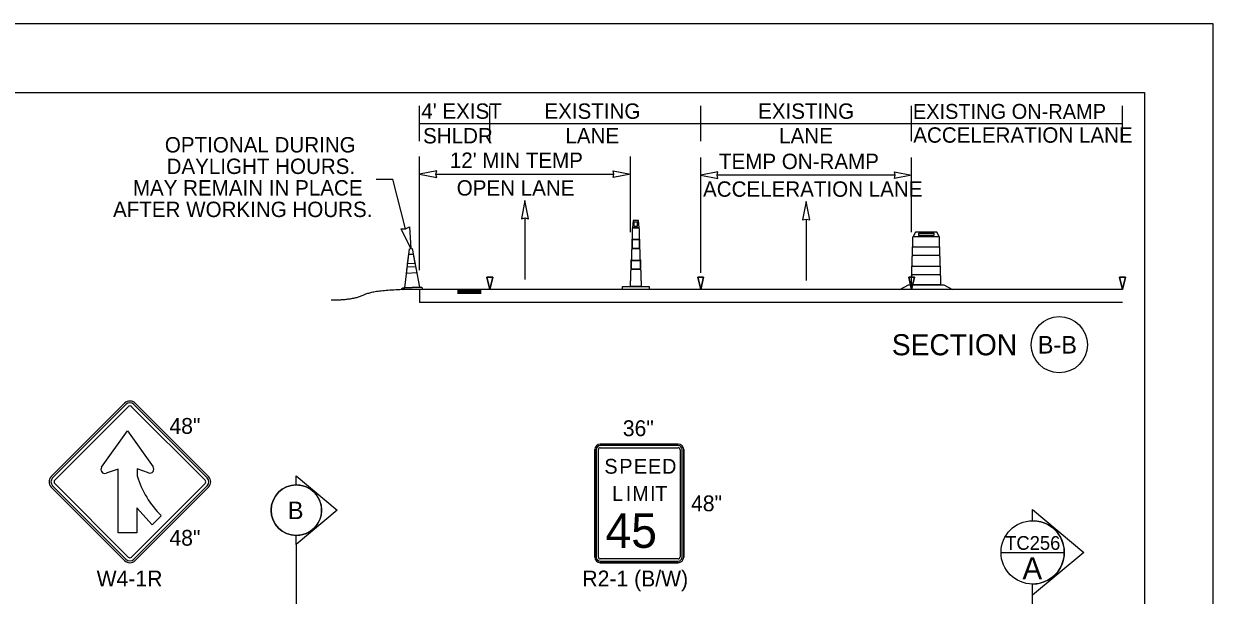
# Model space of a CAD drawing. Extents: x 99999 to 100116, y 99995 to 100013.
# Drawn here: x 100050.65 to 100056.06, y 100008.09 to 100010.69 of the extents above; entities that cross this region are included whole.
import ezdxf

# ---------------------------------------------------------------- set-up
doc = ezdxf.new("R2010")
doc.units = 0
for name, color, linetype in [('SH_GI_PlotLimits', 7, 'Continuous'), ('SH_GI_SectionCut', 7, 'Continuous'), ('SH_GI_SheetBorder', 7, 'Continuous'), ('SH_TI_WZSectionCut', 7, 'Continuous'), ('TR_SN_ConstructionSigns', 7, 'Continuous'), ('TR_WZ_ArrowLeftStrRightTurn', 7, 'Continuous'), ('TR_WZ_TallChanDeviceElev', 7, 'Continuous'), ('TR_WZ_TrafficConeElev', 7, 'Continuous'), ('TR_WZ_TrafficSafetyDrumElev', 7, 'Continuous'), ('TR_WZ_WorkZoneDetails', 7, 'Continuous'), ('TR_WZ_WorkZoneTextCurrent', 7, 'Continuous')]:
    doc.layers.add(name, color=color, linetype=linetype)

msp = doc.modelspace()

# ---------------------------------------------------------------- linework, layer by layer
at = {"layer": 'SH_GI_PlotLimits'}
msp.add_lwpolyline([(100039.0625, 99999.6875), (100056.0625, 99999.6875), (100056.0625, 100010.6875), (100039.0625, 100010.6875)], close=True, dxfattribs=at)
at = {"layer": 'SH_GI_SectionCut'}
for p, q in [((100051.8894, 100008.589), (100051.8894, 100008.6297)), ((100051.8894, 100008.6297), (100052.0755, 100008.4738)), ((100052.0755, 100008.4738), (100051.8894, 100008.3179)), ((100055.2407, 100008.4258), (100055.2407, 100008.4767)), ((100055.2407, 100008.4767), (100055.4733, 100008.2818)), ((100051.8894, 100008.3179), (100051.8894, 100008.3586)), ((100051.8894, 100008.3179), (100051.8894, 100006.8828)), ((100055.4733, 100008.2818), (100055.2407, 100008.0869)), ((100055.2407, 100008.0869), (100055.2407, 100008.1378)), ((100055.2407, 100006.7109), (100055.2407, 100008.0869))]:
    msp.add_line(p, q, dxfattribs=at)
msp.add_lwpolyline([(100055.0967, 100008.2818), (100055.3847, 100008.2818)], dxfattribs=at)
for centre, radius in [((100051.8894, 100008.4738), 0.1152), ((100051.8894, 100008.4738), 0.1152), ((100055.2407, 100008.2818), 0.144)]:
    msp.add_circle(centre, radius, dxfattribs=at)
for centre, radius, start, end in [((100051.8894, 100008.4738), 0.1152, 90.0022, 269.9978), ((100051.8894, 100008.4738), 0.1152, 269.9978, 90.0022), ((100051.8894, 100008.4738), 0.1152, 269.9978, 90.0022), ((100055.2407, 100008.2818), 0.144, 269.9978, 90.0022)]:
    msp.add_arc(centre, radius, start, end, dxfattribs=at)
at = {"layer": 'SH_GI_SheetBorder'}
for p, q in [((100040, 100010.375), (100055.75, 100010.375)), ((100055.75, 100010.375), (100055.75, 100000))]:
    msp.add_line(p, q, dxfattribs=at)
at = {"layer": 'SH_TI_WZSectionCut'}
for p, q in [((100052.45, 100009.5666), (100052.45, 100010.0836)), ((100053.41, 100009.7388), (100053.41, 100010.0836)), ((100052.525, 100010.0036), (100053.335, 100010.0036))]:
    msp.add_line(p, q, dxfattribs=at)
for points in [[(100052.45, 100010.0036), (100052.5286, 100009.9882), (100052.525, 100010.0036), (100052.5286, 100010.019)], [(100053.41, 100010.0036), (100053.3314, 100009.9882), (100053.335, 100010.0036), (100053.3314, 100010.019)]]:
    msp.add_lwpolyline(points, close=True, dxfattribs=at)
at = {"layer": 'TR_SN_ConstructionSigns'}
for p, q in [((100051.1081, 100008.9607), (100050.774, 100008.6266)), ((100051.1141, 100008.9548), (100050.78, 100008.6207)), ((100050.7899, 100008.6107), (100051.124, 100008.9448)), ((100051.1399, 100008.9448), (100051.4741, 100008.6107)), ((100051.484, 100008.6207), (100051.1499, 100008.9548)), ((100051.49, 100008.6266), (100051.1559, 100008.9607)), ((100051.0032, 100008.669), (100051.121, 100008.8347)), ((100051.121, 100008.8347), (100051.2375, 100008.6708)), ((100053.2728, 100008.7749), (100053.6272, 100008.7749)), ((100053.6272, 100008.7749), (100053.2728, 100008.7749)), ((100053.2475, 100008.2602), (100053.2475, 100008.7496)), ((100053.2475, 100008.7496), (100053.2475, 100008.2602)), ((100053.2546, 100008.7496), (100053.2546, 100008.2602)), ((100053.2644, 100008.2602), (100053.2644, 100008.7496)), ((100053.6272, 100008.7679), (100053.2728, 100008.7679)), ((100053.2728, 100008.758), (100053.6272, 100008.758)), ((100053.6357, 100008.7496), (100053.6357, 100008.2602)), ((100053.6455, 100008.2602), (100053.6455, 100008.7496)), ((100053.6525, 100008.7496), (100053.6525, 100008.2602)), ((100053.6525, 100008.2602), (100053.6525, 100008.7496)), ((100051.0784, 100008.6609), (100051.0235, 100008.6419)), ((100051.0784, 100008.3708), (100051.0784, 100008.6609)), ((100051.2171, 100008.6438), (100051.1652, 100008.6624)), ((100051.1652, 100008.6624), (100051.1652, 100008.63)), ((100050.774, 100008.5789), (100051.1081, 100008.2448)), ((100050.78, 100008.5849), (100051.1141, 100008.2508)), ((100051.124, 100008.2607), (100050.7899, 100008.5948)), ((100051.4741, 100008.5948), (100051.1399, 100008.2607)), ((100051.1499, 100008.2508), (100051.484, 100008.5849)), ((100051.1559, 100008.2448), (100051.49, 100008.5789)), ((100051.2329, 100008.4077), (100051.1637, 100008.4842)), ((100051.1637, 100008.4842), (100051.1637, 100008.3708)), ((100051.2741, 100008.4489), (100051.2329, 100008.4077)), ((100051.1637, 100008.3708), (100051.0784, 100008.3708)), ((100053.6272, 100008.2518), (100053.2728, 100008.2518)), ((100053.2728, 100008.2419), (100053.6272, 100008.2419)), ((100053.6272, 100008.2349), (100053.2728, 100008.2349)), ((100053.2728, 100008.2349), (100053.6272, 100008.2349))]:
    msp.add_line(p, q, dxfattribs=at)
for centre, radius, start, end in [((100051.132, 100008.9369), 0.0338, 45, 135), ((100051.132, 100008.9369), 0.0253, 45, 135), ((100051.132, 100008.9369), 0.0113, 45, 135), ((100053.2728, 100008.7496), 0.0253, 90, 180), ((100053.2728, 100008.7496), 0.0253, 90, 180), ((100053.6272, 100008.7496), 0.0253, 360, 90), ((100053.6272, 100008.7496), 0.0253, 360, 90), ((100053.2728, 100008.7496), 0.0183, 90, 180), ((100053.2728, 100008.7496), 0.00844, 90, 180), ((100053.6272, 100008.7496), 0.0183, 0, 90), ((100053.6272, 100008.7496), 0.00844, 360, 90), ((100051.0177, 100008.6587), 0.0177, 144.5862, 289.1062), ((100051.2231, 100008.6606), 0.0177, 250.3331, 35.4138), ((100050.7979, 100008.6028), 0.0338, 135, 225), ((100050.7979, 100008.6028), 0.0253, 135, 225), ((100050.7979, 100008.6028), 0.0113, 135, 225), ((100051.5783, 100008.7551), 0.4316, 196.843, 225.185), ((100051.4661, 100008.6028), 0.0113, 315, 45), ((100051.4661, 100008.6028), 0.0253, 315, 45), ((100051.4661, 100008.6028), 0.0338, 315, 45), ((100051.132, 100008.2687), 0.0338, 225, 315), ((100051.132, 100008.2687), 0.0253, 225, 315), ((100051.132, 100008.2687), 0.0113, 225, 315), ((100053.2728, 100008.2602), 0.0253, 180, 270), ((100053.2728, 100008.2602), 0.0253, 180, 270), ((100053.2728, 100008.2602), 0.0183, 180, 270), ((100053.2728, 100008.2602), 0.00844, 180, 270), ((100053.6272, 100008.2602), 0.0253, 270, 360), ((100053.6272, 100008.2602), 0.0183, 270, 360), ((100053.6272, 100008.2602), 0.00844, 270, 0), ((100053.6272, 100008.2602), 0.0253, 270, 360)]:
    msp.add_arc(centre, radius, start, end, dxfattribs=at)
at = {"layer": 'TR_WZ_ArrowLeftStrRightTurn'}
for p, q in [((100052.93, 100009.8039), (100052.93, 100009.524)), ((100054.21, 100009.7986), (100054.21, 100009.5187))]:
    msp.add_line(p, q, dxfattribs=at)
for points in [[(100052.93, 100009.884), (100052.9135, 100009.8), (100052.93, 100009.8039), (100052.9465, 100009.8)], [(100054.21, 100009.8787), (100054.1935, 100009.7947), (100054.21, 100009.7986), (100054.2265, 100009.7947)]]:
    msp.add_lwpolyline(points, close=True, dxfattribs=at)
at = {"layer": 'TR_WZ_TallChanDeviceElev'}
for p, q in [((100053.4494, 100009.7588), (100053.42, 100009.7588)), ((100053.42, 100009.7588), (100053.4494, 100009.7588)), ((100053.42, 100009.7588), (100053.4494, 100009.7588)), ((100053.4422, 100009.7848), (100053.4266, 100009.7848)), ((100053.4266, 100009.767), (100053.4422, 100009.767)), ((100053.4178, 100009.7051), (100053.4515, 100009.7051)), ((100053.4178, 100009.6655), (100053.4178, 100009.7051)), ((100053.4515, 100009.7051), (100053.4515, 100009.6655)), ((100053.4515, 100009.6655), (100053.4178, 100009.6655)), ((100053.4139, 100009.5707), (100053.4139, 100009.6103)), ((100053.4139, 100009.6103), (100053.4555, 100009.6103)), ((100053.4555, 100009.6103), (100053.4555, 100009.5707)), ((100053.4555, 100009.5707), (100053.4139, 100009.5707)), ((100053.3747, 100009.4788), (100053.3747, 100009.492)), ((100053.4947, 100009.4788), (100053.3747, 100009.4788)), ((100053.4947, 100009.492), (100053.4947, 100009.4788))]:
    msp.add_line(p, q, dxfattribs=at)
for points in [[(100053.4198, 100009.7106), (100053.4198, 100009.7555)], [(100053.4198, 100009.7106), (100053.4198, 100009.7555)], [(100053.4496, 100009.7555), (100053.4496, 100009.7106)], [(100053.4496, 100009.7555), (100053.4496, 100009.7106)], [(100053.4178, 100009.6632), (100053.4178, 100009.7074)], [(100053.4178, 100009.6632), (100053.4178, 100009.7074)], [(100053.4515, 100009.7074), (100053.4515, 100009.6632)], [(100053.4515, 100009.7074), (100053.4515, 100009.6632)], [(100053.4159, 100009.6158), (100053.4159, 100009.66)], [(100053.4159, 100009.6158), (100053.4159, 100009.66)], [(100053.4535, 100009.66), (100053.4535, 100009.6158)], [(100053.4535, 100009.66), (100053.4535, 100009.6158)], [(100053.4139, 100009.5685), (100053.4139, 100009.6125)], [(100053.4139, 100009.5685), (100053.4139, 100009.6125)], [(100053.4555, 100009.6125), (100053.4555, 100009.5685)], [(100053.4555, 100009.6125), (100053.4555, 100009.5685)], [(100053.412, 100009.5212), (100053.412, 100009.5653)], [(100053.412, 100009.5212), (100053.412, 100009.5653)], [(100053.4574, 100009.5653), (100053.4574, 100009.5212)], [(100053.4574, 100009.5653), (100053.4574, 100009.5212)], [(100053.3747, 100009.492), (100053.41, 100009.492), (100053.4594, 100009.492), (100053.4947, 100009.492)], [(100053.4594, 100009.492), (100053.41, 100009.492), (100053.41, 100009.518)], [(100053.4594, 100009.492), (100053.41, 100009.492), (100053.41, 100009.518)], [(100053.4594, 100009.518), (100053.4594, 100009.492)], [(100053.4594, 100009.518), (100053.4594, 100009.492)]]:
    msp.add_lwpolyline(points, dxfattribs=at)
for points in [[(100053.4494, 100009.7588), (100053.4467, 100009.793), (100053.4225, 100009.793), (100053.42, 100009.7588)], [(100053.4515, 100009.7051), (100053.4178, 100009.7051), (100053.4178, 100009.6655), (100053.4515, 100009.6655)], [(100053.4555, 100009.6103), (100053.4139, 100009.6103), (100053.4139, 100009.5707), (100053.4555, 100009.5707)]]:
    msp.add_lwpolyline(points, close=True, dxfattribs=at)
for centre, major_axis, ratio, start_param, end_param in [((100053.42, 100009.7548), (0, 0.00412), 0.059356, 0.177149, 1.393647), ((100053.42, 100009.7548), (0, 0.00412), 0.059356, 0.177149, 1.393647), ((100053.4266, 100009.7759), (0, 0.00891), 0.07945, 0, 3.141593), ((100053.4422, 100009.7759), (0, 0.00891), 0.07945, 3.141593, 6.283185), ((100053.4493, 100009.7548), (0, 0.00412), 0.059356, 4.889538, 6.106036), ((100053.4493, 100009.7548), (0, 0.00412), 0.059356, 4.889538, 6.106036), ((100053.4214, 100009.7047), (0, 0.00651), 0.609371, 0.4288, 1.141997), ((100053.4214, 100009.7047), (0, 0.00651), 0.609371, 0.4288, 1.141997), ((100053.4479, 100009.7047), (0, 0.00651), 0.609371, 5.141189, 5.854386), ((100053.4479, 100009.7047), (0, 0.00651), 0.609371, 5.141189, 5.854386), ((100053.4195, 100009.6573), (0, 0.00651), 0.609371, 0.4288, 1.141997), ((100053.4195, 100009.6573), (0, 0.00651), 0.609371, 0.4288, 1.141997), ((100053.4499, 100009.6573), (0, 0.00651), 0.609371, 5.141189, 5.854386), ((100053.4499, 100009.6573), (0, 0.00651), 0.609371, 5.141189, 5.854386), ((100053.4175, 100009.6098), (0, 0.00651), 0.609371, 0.4288, 1.141997), ((100053.4175, 100009.6098), (0, 0.00651), 0.609371, 0.4288, 1.141997), ((100053.4519, 100009.6098), (0, 0.00651), 0.609371, 5.141189, 5.854386), ((100053.4519, 100009.6098), (0, 0.00651), 0.609371, 5.141189, 5.854386), ((100053.4156, 100009.5625), (0, 0.00651), 0.609371, 0.4288, 1.141997), ((100053.4156, 100009.5625), (0, 0.00651), 0.609371, 0.4288, 1.141997), ((100053.4538, 100009.5625), (0, 0.00651), 0.609371, 5.141189, 5.854386), ((100053.4538, 100009.5625), (0, 0.00651), 0.609371, 5.141189, 5.854386), ((100053.4136, 100009.5153), (0, 0.00651), 0.609371, 0.4288, 1.141997), ((100053.4136, 100009.5153), (0, 0.00651), 0.609371, 0.4288, 1.141997), ((100053.4558, 100009.5153), (0, 0.00651), 0.609371, 5.141189, 5.854386), ((100053.4558, 100009.5153), (0, 0.00651), 0.609371, 5.141189, 5.854386)]:
    msp.add_ellipse(centre, major_axis=major_axis, ratio=ratio, start_param=start_param, end_param=end_param, dxfattribs=at)
at = {"layer": 'TR_WZ_TrafficConeElev'}
for p, q in [((100052.3959, 100009.5953), (100052.4011, 100009.6388)), ((100052.4011, 100009.6388), (100052.4213, 100009.6395)), ((100052.4213, 100009.6395), (100052.4294, 100009.5964)), ((100052.3908, 100009.5518), (100052.3944, 100009.5819)), ((100052.3944, 100009.5819), (100052.4319, 100009.5832)), ((100052.4294, 100009.5964), (100052.3959, 100009.5953)), ((100052.4319, 100009.5832), (100052.4375, 100009.5534)), ((100052.4375, 100009.5534), (100052.3908, 100009.5518)), ((100052.3702, 100009.4827), (100052.3735, 100009.4861)), ((100052.3705, 100009.476), (100052.3702, 100009.4827)), ((100052.4629, 100009.4792), (100052.3705, 100009.476)), ((100052.4497, 100009.4887), (100052.4592, 100009.4891)), ((100052.4592, 100009.4891), (100052.4627, 100009.4858)), ((100052.4627, 100009.4858), (100052.4629, 100009.4792))]:
    msp.add_line(p, q, dxfattribs=at)
msp.add_lwpolyline([(100052.4497, 100009.4887), (100052.383, 100009.4865), (100052.4041, 100009.664), (100052.4166, 100009.6644)], close=True, dxfattribs=at)
msp.add_lwpolyline([(100052.4497, 100009.4887), (100052.383, 100009.4865), (100052.4041, 100009.664), (100052.4166, 100009.6644)], close=True, dxfattribs=at)
msp.add_lwpolyline([(100052.3735, 100009.4861), (100052.383, 100009.4865), (100052.4497, 100009.4887)], dxfattribs=at)
at = {"layer": 'TR_WZ_TrafficSafetyDrumElev'}
for p, q in [((100054.6967, 100009.7188), (100054.8151, 100009.7188)), ((100054.6967, 100009.7188), (100054.8151, 100009.7188)), ((100054.7243, 100009.734), (100054.7897, 100009.734)), ((100054.7897, 100009.7236), (100054.7243, 100009.7236)), ((100054.6944, 100009.6724), (100054.8174, 100009.6724)), ((100054.6944, 100009.6325), (100054.6944, 100009.6724)), ((100054.8174, 100009.6724), (100054.8174, 100009.6325)), ((100054.6915, 100009.5844), (100054.8203, 100009.5844)), ((100054.6915, 100009.5445), (100054.6915, 100009.5844)), ((100054.8174, 100009.6325), (100054.6944, 100009.6325)), ((100054.8203, 100009.5844), (100054.8203, 100009.5445)), ((100054.8203, 100009.5445), (100054.6915, 100009.5445))]:
    msp.add_line(p, q, dxfattribs=at)
for points in [[(100054.6959, 100009.676), (100054.6959, 100009.7172)], [(100054.6959, 100009.676), (100054.6959, 100009.7172)], [(100054.8159, 100009.7172), (100054.8159, 100009.676)], [(100054.8159, 100009.7172), (100054.8159, 100009.676)], [(100054.6944, 100009.632), (100054.6944, 100009.673)], [(100054.6944, 100009.632), (100054.6944, 100009.673)], [(100054.8174, 100009.673), (100054.8174, 100009.632)], [(100054.8174, 100009.673), (100054.8174, 100009.632)], [(100054.6915, 100009.5439), (100054.6915, 100009.5849)], [(100054.6915, 100009.5439), (100054.6915, 100009.5849)], [(100054.693, 100009.5879), (100054.693, 100009.629)], [(100054.693, 100009.5879), (100054.693, 100009.629)], [(100054.8189, 100009.629), (100054.8189, 100009.5879)], [(100054.8189, 100009.629), (100054.8189, 100009.5879)], [(100054.8203, 100009.5849), (100054.8203, 100009.5439)], [(100054.8203, 100009.5849), (100054.8203, 100009.5439)], [(100054.8218, 100009.5409), (100054.8218, 100009.4988), (100054.69, 100009.4988), (100054.69, 100009.5409)], [(100054.8218, 100009.5409), (100054.8218, 100009.4988), (100054.69, 100009.4988), (100054.69, 100009.5409)]]:
    msp.add_lwpolyline(points, dxfattribs=at)
for points in [[(100054.8151, 100009.7188), (100054.8046, 100009.7388), (100054.7072, 100009.7388), (100054.6967, 100009.7188)], [(100054.6359, 100009.4788), (100054.6761, 100009.4988), (100054.8357, 100009.4988), (100054.8759, 100009.4788)]]:
    msp.add_lwpolyline(points, close=True, dxfattribs=at)
for centre, major_axis, ratio, start_param, end_param in [((100054.6969, 100009.7168), (0, 0.00199), 0.493438, 0.177149, 1.393647), ((100054.6969, 100009.7168), (0, 0.00199), 0.493438, 0.177149, 1.393647), ((100054.7243, 100009.7288), (0, 0.0052), 0.570305, 0, 3.141593), ((100054.7897, 100009.7288), (0, 0.0052), 0.570305, 3.141593, 6.283185), ((100054.8149, 100009.7168), (0, 0.00199), 0.493438, 4.889538, 6.106036), ((100054.8149, 100009.7168), (0, 0.00199), 0.493438, 4.889538, 6.106036), ((100054.6972, 100009.6705), (0, 0.00606), 0.493438, 0.4288, 1.141997), ((100054.6972, 100009.6705), (0, 0.00606), 0.493438, 0.4288, 1.141997), ((100054.8147, 100009.6705), (0, 0.00606), 0.493438, 5.141189, 5.854386), ((100054.8147, 100009.6705), (0, 0.00606), 0.493438, 5.141189, 5.854386), ((100054.6942, 100009.5824), (0, 0.00606), 0.493438, 0.4288, 1.141997), ((100054.6942, 100009.5824), (0, 0.00606), 0.493438, 0.4288, 1.141997), ((100054.6957, 100009.6265), (0, 0.00606), 0.493438, 0.4288, 1.141997), ((100054.6957, 100009.6265), (0, 0.00606), 0.493438, 0.4288, 1.141997), ((100054.8161, 100009.6265), (0, 0.00606), 0.493438, 5.141189, 5.854386), ((100054.8161, 100009.6265), (0, 0.00606), 0.493438, 5.141189, 5.854386), ((100054.8176, 100009.5824), (0, 0.00606), 0.493438, 5.141189, 5.854386), ((100054.8176, 100009.5824), (0, 0.00606), 0.493438, 5.141189, 5.854386), ((100054.6927, 100009.5384), (0, 0.00606), 0.493438, 0.4288, 1.141997), ((100054.6927, 100009.5384), (0, 0.00606), 0.493438, 0.4288, 1.141997), ((100054.8191, 100009.5384), (0, 0.00606), 0.493438, 5.141189, 5.854386), ((100054.8191, 100009.5384), (0, 0.00606), 0.493438, 5.141189, 5.854386)]:
    msp.add_ellipse(centre, major_axis=major_axis, ratio=ratio, start_param=start_param, end_param=end_param, dxfattribs=at)
at = {"layer": 'TR_WZ_WorkZoneDetails'}
for p, q in [((100052.45, 100010.154), (100052.45, 100010.314)), ((100052.77, 100010.154), (100052.77, 100010.314)), ((100053.73, 100010.154), (100053.73, 100010.314)), ((100054.69, 100010.154), (100054.69, 100010.314)), ((100055.65, 100010.154), (100055.65, 100010.314)), ((100052.45, 100010.234), (100052.77, 100010.234)), ((100052.77, 100010.234), (100053.73, 100010.234)), ((100053.73, 100010.234), (100054.69, 100010.234)), ((100054.69, 100010.234), (100055.65, 100010.234)), ((100053.73, 100009.5546), (100053.73, 100010.0783)), ((100054.69, 100009.7388), (100054.69, 100010.0783)), ((100052.2522, 100009.9799), (100052.3284, 100009.9799)), ((100052.3868, 100009.7549), (100052.3284, 100009.9799)), ((100054.615, 100009.9983), (100053.805, 100009.9983)), ((100055.65, 100009.4787), (100052.45, 100009.4787)), ((100052.45, 100009.4787), (100052.45, 100009.4187)), ((100052.6236, 100009.4746), (100052.73, 100009.4746)), ((100052.6236, 100009.4701), (100052.73, 100009.4701)), ((100052.6236, 100009.4655), (100052.73, 100009.4655)), ((100052.6236, 100009.4614), (100052.73, 100009.4614)), ((100055.65, 100009.4187), (100052.45, 100009.4187))]:
    msp.add_line(p, q, dxfattribs=at)
for points in [[(100053.73, 100009.9983), (100053.8086, 100009.9829), (100053.805, 100009.9983), (100053.8086, 100010.0137)], [(100054.69, 100009.9983), (100054.6114, 100009.9829), (100054.615, 100009.9983), (100054.6114, 100010.0137)], [(100052.4103, 100009.6642), (100052.367, 100009.7545), (100052.3868, 100009.7549), (100052.4044, 100009.7641)], [(100052.77, 100009.4787), (100052.7566, 100009.5346), (100052.7833, 100009.5346)], [(100053.73, 100009.4787), (100053.7166, 100009.5346), (100053.7433, 100009.5346)], [(100054.69, 100009.4787), (100054.6766, 100009.5346), (100054.7033, 100009.5346)], [(100055.65, 100009.4787), (100055.6366, 100009.5346), (100055.6633, 100009.5346)]]:
    msp.add_lwpolyline(points, close=True, dxfattribs=at)
for points in [[(100052.7833, 100009.5346), (100052.7566, 100009.5346), (100052.77, 100009.4787), (100052.7833, 100009.5346)], [(100053.7433, 100009.5346), (100053.7166, 100009.5346), (100053.73, 100009.4787), (100053.7433, 100009.5346)], [(100054.7033, 100009.5346), (100054.6766, 100009.5346), (100054.69, 100009.4787), (100054.7033, 100009.5346)], [(100055.6633, 100009.5346), (100055.6366, 100009.5346), (100055.65, 100009.4787), (100055.6633, 100009.5346)]]:
    msp.add_lwpolyline(points, dxfattribs=at)
msp.add_circle((100055.3621, 100009.2268), 0.128, dxfattribs=at)
msp.add_open_spline([(100052.45, 100009.4787), (100052.2491, 100009.4787), (100052.1487, 100009.429), (100052.0483, 100009.429)], degree=2, dxfattribs=at)

# ---------------------------------------------------------------- texts
at = {"layer": 'SH_GI_SectionCut'}
for s, height, rotation, p in [('B', 0.08, 0.01, (100051.8507, 100008.4331)), ('A', 0.1, 359.99, (100055.1945, 100008.1598))]:
    msp.add_text(s, height=height, rotation=rotation, dxfattribs=at).set_placement(p)
msp.add_text('TC256', height=0.0625, dxfattribs=at).set_placement((100055.1158, 100008.2934))
at = {"layer": 'TR_SN_ConstructionSigns'}
for s, height, p in [('48"', 0.072, (100051.3118, 100008.8213)), ('36"', 0.072, (100053.3753, 100008.8109)), ('S', 0.0675, (100053.2914, 100008.6399)), ('P', 0.0675, (100053.3596, 100008.6399)), ('E', 0.0675, (100053.4257, 100008.6399)), ('E', 0.0675, (100053.4899, 100008.6399)), ('D', 0.0675, (100053.554, 100008.6399)), ('L', 0.0675, (100053.3265, 100008.5162)), ('I', 0.0675, (100053.3886, 100008.5162)), ('M', 0.0675, (100053.4183, 100008.5162)), ('I', 0.0675, (100053.4993, 100008.5162)), ('T', 0.0675, (100053.5229, 100008.5162)), ('48"', 0.072, (100053.6858, 100008.4689)), ('48"', 0.072, (100051.3118, 100008.3122)), ('W4-1R', 0.072, (100050.9805, 100008.1269)), ('R2-1 (B/W)', 0.072, (100053.1913, 100008.1269))]:
    msp.add_text(s, height=height, rotation=360, dxfattribs=at).set_placement(p)
msp.add_text('45', height=0.1575, dxfattribs=at).set_placement((100053.2965, 100008.3024))
at = {"layer": 'TR_WZ_WorkZoneDetails'}
for s, height, p in [("4' EXIST", 0.07, (100052.4583, 100010.255)), ('EXISTING', 0.07, (100053.0185, 100010.255)), ('EXISTING', 0.07, (100053.9912, 100010.255)), ('EXISTING ON-RAMP', 0.068, (100054.6955, 100010.2547)), ('SHLDR', 0.07, (100052.4663, 100010.143)), ('LANE', 0.07, (100053.1142, 100010.143)), ('LANE', 0.07, (100054.0869, 100010.143)), ('ACCELERATION LANE', 0.07, (100054.6973, 100010.1463)), ("12' MIN TEMP", 0.07, (100052.5882, 100010.0316)), ('TEMP ON-RAMP', 0.07, (100053.8129, 100010.0263)), ('OPEN LANE', 0.07, (100052.6194, 100009.9056)), ('ACCELERATION LANE', 0.07, (100053.7405, 100009.9003))]:
    msp.add_text(s, height=height, dxfattribs=at).set_placement(p)
for s, height, p in [('SECTION', 0.096, (100054.5996, 100009.1788)), ('B-B', 0.08, (100055.264, 100009.1868))]:
    msp.add_text(s, height=height, rotation=360, dxfattribs=at).set_placement(p)
at = {"layer": 'TR_WZ_WorkZoneTextCurrent'}
for s, p in [('OPTIONAL DURING', (100051.291, 100010.1019)), ('DAYLIGHT HOURS.', (100051.2989, 100010.0039)), ('MAY REMAIN IN PLACE', (100051.1453, 100009.9059)), ('AFTER WORKING HOURS.', (100051.0552, 100009.8079))]:
    msp.add_text(s, height=0.07, dxfattribs=at).set_placement(p)

doc.saveas('drawing.dxf')
